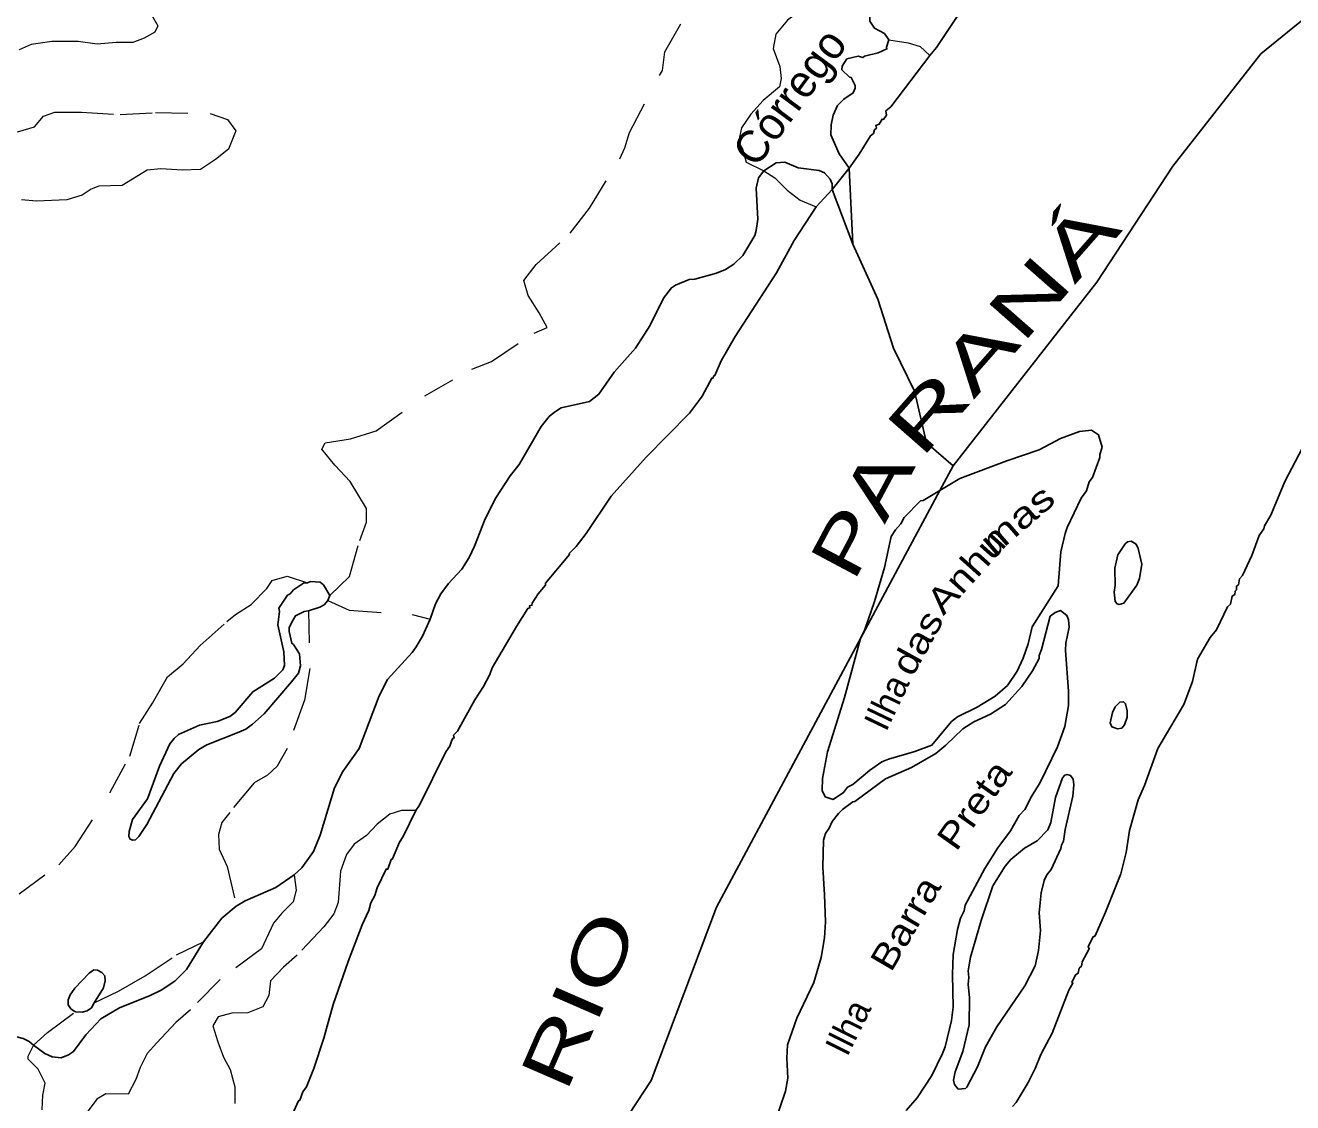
# Model space of a CAD drawing. Extents: x 344.9 to 371, y 7566.4 to 7594.3.
# Drawn here: x 362.817 to 366.76, y 7570.925 to 7574.277 of the extents above; entities that cross this region are included whole.
import ezdxf
from ezdxf.enums import TextEntityAlignment as Align

# ---------------------------------------------------------------- set-up
doc = ezdxf.new("R2010")
doc.units = 0
doc.header["$LTSCALE"] = 0.04
doc.linetypes.add('SHORT_DASHED', pattern=[2.7, 1.5, -1.2])
for name, color, linetype, lineweight in [('17', 7, 'SHORT_DASHED', 13), ('2', 7, 'Continuous', 25), ('21', 7, 'SHORT_DASHED', 13), ('55', 7, 'Continuous', 25), ('7', 7, 'Continuous', 25)]:
    doc.layers.add(name, color=color, linetype=linetype, lineweight=lineweight)
doc.layers.add('61', color=7, linetype='Continuous')

msp = doc.modelspace()

# ---------------------------------------------------------------- linework, layer by layer
at = {"layer": '17'}
for points in [[(365.3482, 7574.5062), (365.2817, 7574.4942), (365.2493, 7574.4831), (365.2438, 7574.4498), (365.2447, 7574.3657), (365.2401, 7574.3324), (365.1883, 7574.294), (365.1514, 7574.2497), (365.144, 7574.2053), (365.1643, 7574.1489), (365.168, 7574.112), (365.1634, 7574.0865), (365.1125, 7574.0431), (365.0737, 7574.0015), (365.0451, 7573.959), (365.0358, 7573.9146), (365.0478, 7573.893), (365.0599, 7573.8514), (365.1141, 7573.8251)], [(363.7646, 7572.5029), (363.8257, 7572.5619), (363.8573, 7572.6744), (363.8788, 7572.7313), (363.8788, 7572.7742), (363.827, 7572.8576), (363.7802, 7572.9082), (363.7398, 7572.9587), (363.7499, 7572.9783), (363.8283, 7572.991), (363.9079, 7573.015), (364.0595, 7573.1249), (364.2061, 7573.2077), (364.2667, 7573.2317), (364.3995, 7573.3195), (364.4399, 7573.3372), (364.4159, 7573.3827), (364.3818, 7573.4371), (364.3679, 7573.4838), (364.4058, 7573.5331), (364.5119, 7573.6304), (364.5726, 7573.7082), (364.6661, 7573.8623), (364.6825, 7573.8964), (364.6964, 7573.9444), (364.7988, 7574.1371), (364.8063, 7574.1953), (364.8961, 7574.3501)], [(365.5038, 7574.2325), (365.5635, 7574.2231), (365.6005, 7574.212), (365.6308, 7574.1841)], [(365.1141, 7573.8251), (365.1486, 7573.8024), (365.1874, 7573.7645), (365.2272, 7573.7331), (365.2774, 7573.7122)], [(362.7973, 7571.5743), (362.9208, 7571.6646), (362.9714, 7571.7215), (363.0813, 7571.8908), (363.142, 7572.0033), (363.1724, 7572.1045), (363.2128, 7572.1677), (363.2596, 7572.2498), (363.3076, 7572.2903), (363.3606, 7572.3471), (363.444, 7572.4217), (363.4706, 7572.4444), (363.5199, 7572.4747), (363.568, 7572.5253), (363.5844, 7572.5493), (363.6311, 7572.5632), (363.6948, 7572.5426)], [(363.7584, 7572.487), (363.8245, 7572.4571), (364.0203, 7572.4444), (364.076, 7572.4291)], [(363.6981, 7572.4554), (363.7018, 7572.2754), (363.6852, 7572.1776), (363.6317, 7572.0272), (363.6003, 7571.9719), (363.5708, 7571.9442), (363.5284, 7571.9202), (363.4527, 7571.828), (363.4287, 7571.7966), (363.4177, 7571.7597), (363.4195, 7571.7136), (363.4453, 7571.6601), (363.4733, 7571.5357)], [(364.0315, 7571.8336), (363.9873, 7571.8338), (363.9504, 7571.8228), (363.9117, 7571.7914), (363.8785, 7571.7563), (363.8397, 7571.7287), (363.8157, 7571.6973), (363.7973, 7571.6456), (363.7899, 7571.5479), (363.777, 7571.5128), (363.7456, 7571.4722), (363.6626, 7571.3837), (363.6202, 7571.3468), (363.5796, 7571.3043), (363.5741, 7571.2581), (363.5557, 7571.2231), (363.5095, 7571.2046), (363.4597, 7571.2028), (363.4173, 7571.1917), (363.4007, 7571.1641), (363.4154, 7571.1142), (363.4339, 7571.0663), (363.4542, 7571.0275), (363.4689, 7570.974), (363.4689, 7570.9224)], [(363.6536, 7571.6334), (363.6591, 7571.5864), (363.6499, 7571.5495), (363.6149, 7571.5144), (363.589, 7571.483), (363.5521, 7571.4037), (363.423, 7571.3078), (363.3307, 7571.2137), (363.2846, 7571.174), (363.2255, 7571.1113), (363.196, 7571.0781), (363.1739, 7571.0338), (363.161, 7570.9969), (363.137, 7570.9508), (363.0669, 7570.9526), (363.0392, 7570.936), (362.9875, 7570.8659)], [(363.031, 7571.2357), (363.1068, 7571.2719), (363.1898, 7571.3198), (363.2876, 7571.3844), (363.371, 7571.425)], [(362.8425, 7571.1035), (362.886, 7571.1435), (362.9726, 7571.2077)], [(362.8694, 7570.9019), (362.8713, 7570.948), (362.8787, 7570.9849), (362.8565, 7571.0292), (362.8252, 7571.0605), (362.8252, 7571.0697), (362.842, 7571.103), (362.8425, 7571.1035)]]:
    msp.add_lwpolyline(points, dxfattribs=at)
at = {"layer": '2'}
for points in [[(366.6473, 7575.1385), (366.451, 7574.9644), (366.3924, 7574.9074), (366.3011, 7574.8304), (366.2082, 7574.7756), (366.1264, 7574.7375), (366.0406, 7574.6851), (366.0231, 7574.6708), (365.9715, 7574.6184), (365.9199, 7574.5485), (365.8158, 7574.435), (365.7738, 7574.3842), (365.7349, 7574.3333), (365.6515, 7574.2087), (365.6308, 7574.1841)], [(365.6308, 7574.1841), (365.5093, 7574.0236), (365.4943, 7574.0109), (365.4958, 7573.9974), (365.4871, 7573.9847), (365.4823, 7573.9855), (365.4736, 7573.9704), (365.4625, 7573.9657), (365.4649, 7573.9577), (365.4585, 7573.9522), (365.4561, 7573.941), (365.4466, 7573.9339), (365.4107, 7573.8762), (365.3798, 7573.8333), (365.3272, 7573.7664), (365.2774, 7573.7122)], [(365.2774, 7573.7122), (365.2087, 7573.6074), (365.1544, 7573.5075), (365.025, 7573.309), (364.9821, 7573.2335), (364.9622, 7573.1875), (364.9582, 7573.1859), (364.9567, 7573.1795), (364.9523, 7573.1796), (364.9228, 7573.1235), (364.9108, 7573.1078)], [(364.9108, 7573.1078), (364.8831, 7573.0702), (364.7485, 7572.9338), (364.64, 7572.8117), (364.562, 7572.6959), (364.531, 7572.6554), (364.5088, 7572.634), (364.5096, 7572.6308), (364.4357, 7572.5411), (364.4349, 7572.5347), (364.4119, 7572.5085), (364.3937, 7572.4791), (364.3929, 7572.4727), (364.3857, 7572.4712), (364.3865, 7572.4648), (364.3802, 7572.4624), (364.3452, 7572.4069), (364.269, 7572.2782), (364.2618, 7572.2576), (364.242, 7572.2203), (364.215, 7572.1782), (364.161, 7572.0813), (364.1491, 7572.0686), (364.1515, 7572.0599), (364.1475, 7572.0591), (364.1435, 7572.0527), (364.1372, 7572.0337), (364.1252, 7572.0162), (364.0427, 7571.8502), (364.0315, 7571.8336)], [(366.835, 7573.0478), (366.7354, 7572.8579), (366.6917, 7572.7531), (366.6719, 7572.7197), (366.6703, 7572.7102), (366.656, 7572.6896), (366.633, 7572.6276)], [(365.8707, 7572.9222), (365.9707, 7572.9564), (366.0374, 7572.9921), (366.0962, 7573.0135), (366.1343, 7573.0175), (366.1557, 7573.0032), (366.1668, 7572.9643), (366.1597, 7572.9421), (366.1597, 7572.9325), (366.1375, 7572.8698), (366.1272, 7572.8571), (366.1184, 7572.8285), (366.1017, 7572.8055), (366.058, 7572.715), (366.0517, 7572.6959), (366.0382, 7572.6388), (366.0303, 7572.5331), (365.9493, 7572.4053), (365.9373, 7572.3529), (365.9215, 7572.3084), (365.9032, 7572.2671), (365.8722, 7572.2227), (365.8341, 7572.1893), (365.7786, 7572.1551), (365.7166, 7572.1257), (365.6984, 7572.1114), (365.6372, 7572.0376), (365.5848, 7572.0177), (365.5022, 7571.9939), (365.4816, 7571.9852), (365.4434, 7571.9582)], [(365.6623, 7572.8301), (365.7238, 7572.8674), (365.8707, 7572.9222)], [(365.4153, 7572.3691), (365.4291, 7572.3974), (365.4585, 7572.4839), (365.4903, 7572.5903), (365.511, 7572.6864), (365.5244, 7572.7078), (365.5411, 7572.7261), (365.5514, 7572.746), (365.6022, 7572.7976), (365.6102, 7572.7991), (365.6623, 7572.8301)], [(366.633, 7572.6276), (366.6036, 7572.5657), (366.5949, 7572.5545), (366.5917, 7572.5363), (366.5853, 7572.5316), (366.5853, 7572.5212), (366.5806, 7572.5164), (366.5798, 7572.5061), (366.5719, 7572.5014), (366.5663, 7572.4759), (366.5575, 7572.468), (366.5226, 7572.3958), (366.5035, 7572.3719), (366.4638, 7572.3052), (366.4479, 7572.2354), (366.4217, 7572.1639), (366.34, 7572.0273), (366.2987, 7571.9114), (366.2788, 7571.8669), (366.2518, 7571.7716), (366.2415, 7571.7033), (366.2256, 7571.6366), (366.178, 7571.5175), (366.1454, 7571.4436), (366.1391, 7571.4405), (366.124, 7571.4103), (366.1271, 7571.4039), (366.1049, 7571.3634), (366.1025, 7571.3492), (366.0954, 7571.3428), (366.0922, 7571.3277), (366.0843, 7571.3222), (366.0732, 7571.2991), (366.0763, 7571.2968), (366.0636, 7571.2745), (366.012, 7571.1411), (365.9763, 7571.0744), (365.9588, 7571.0315), (365.9365, 7570.9879), (365.8992, 7570.9251), (365.8881, 7570.9124)], [(363.6451, 7572.234), (363.5602, 7572.1347), (363.5237, 7572.1024), (363.5025, 7572.0874), (363.4808, 7572.0773), (363.3816, 7572.0382), (363.3562, 7572.0237), (363.3031, 7571.9787), (363.2786, 7571.9491), (363.1951, 7571.7902), (363.1697, 7571.7528), (363.1595, 7571.7431), (363.1517, 7571.7417), (363.1429, 7571.7445), (363.1392, 7571.7528), (363.1397, 7571.7687), (363.1498, 7571.8057), (363.1969, 7571.8698), (363.2343, 7571.9718), (363.2666, 7572.0415), (363.2795, 7572.0577), (363.2933, 7572.0706), (363.3584, 7572.0991), (363.4142, 7572.1113), (363.4534, 7572.1265), (363.4695, 7572.1394), (363.5249, 7572.2036), (363.5924, 7572.2457), (363.6178, 7572.2719), (363.6234, 7572.2853), (363.621, 7572.3275), (363.6027, 7572.4117), (363.6075, 7572.4537), (363.6059, 7572.464), (363.6329, 7572.5037), (363.6409, 7572.5085), (363.6512, 7572.5212), (363.6822, 7572.541), (363.6948, 7572.5426)], [(363.6948, 7572.5426), (363.7044, 7572.5466), (363.7338, 7572.5442), (363.7441, 7572.5363), (363.7646, 7572.5029), (363.7584, 7572.487)], [(363.7584, 7572.487), (363.7465, 7572.4743), (363.733, 7572.4664), (363.6981, 7572.4554)], [(363.6981, 7572.4554), (363.6845, 7572.4529), (363.6575, 7572.4402), (363.6504, 7572.4275)], [(365.3029, 7571.5715), (365.2981, 7571.6573), (365.3005, 7571.7414), (365.3068, 7571.7621), (365.318, 7571.7788), (365.3267, 7571.8002), (365.3466, 7571.8248), (365.3593, 7571.8375), (365.391, 7571.8605), (365.3974, 7571.8621), (365.4927, 7571.9328), (365.5737, 7571.9677), (365.6499, 7572.0114), (365.6809, 7572.0368), (365.7341, 7572.0884), (365.7682, 7572.1099), (365.8199, 7572.1337), (365.8659, 7572.1639), (365.9167, 7572.2203), (365.9501, 7572.2687), (365.9715, 7572.3068), (365.9707, 7572.3163), (365.9786, 7572.3354), (366.0049, 7572.4386), (366.0208, 7572.4497), (366.0374, 7572.4561), (366.0573, 7572.441), (366.0628, 7572.4275), (366.0642, 7572.4047)], [(363.6504, 7572.4275), (363.6377, 7572.4037), (363.6377, 7572.391), (363.6456, 7572.3544), (363.6512, 7572.3505), (363.6695, 7572.3219), (363.6726, 7572.2846), (363.6663, 7572.2615), (363.6451, 7572.234)], [(366.0642, 7572.4047), (366.0541, 7572.3545), (366.0533, 7572.3322), (366.0628, 7572.2052), (366.0628, 7572.1607), (366.0509, 7572.0956), (366.0279, 7572.0321), (365.9747, 7571.9209), (365.9469, 7571.878), (365.9263, 7571.8367), (365.9088, 7571.8184), (365.8818, 7571.7708), (365.8428, 7571.7176), (365.8024, 7571.6533), (365.7404, 7571.5389), (365.7373, 7571.5214), (365.7261, 7571.4984), (365.7174, 7571.4635), (365.7039, 7571.3857), (365.7015, 7571.3238), (365.7039, 7571.2221), (365.6983, 7571.1808), (365.6785, 7571.0982), (365.6705, 7571.0776), (365.6372, 7571.0093), (365.5911, 7570.9394), (365.557, 7570.9005)], [(365.4434, 7571.9582), (365.3918, 7571.9153), (365.3752, 7571.9066), (365.3624, 7571.8899), (365.3307, 7571.8685), (365.3052, 7571.8764), (365.2957, 7571.8963), (365.2973, 7571.9336), (365.3124, 7572.0162), (365.3656, 7572.1861), (365.4153, 7572.3691)], [(365.7904, 7571.4917), (365.827, 7571.5993), (365.8651, 7571.6604), (365.8826, 7571.6819), (365.9254, 7571.7168), (365.9644, 7571.7398), (365.9977, 7571.774), (366.0072, 7571.7962), (366.0223, 7571.8748), (366.044, 7571.9361), (366.0509, 7571.9435), (366.0587, 7571.9458), (366.0689, 7571.9431), (366.0767, 7571.9315), (366.079, 7571.9135), (366.0758, 7571.8785), (366.0517, 7571.7748), (366.0469, 7571.7383), (366.0406, 7571.7263), (366.039, 7571.7152), (366.008, 7571.6501), (365.9945, 7571.6334), (365.9866, 7571.616), (365.9771, 7571.5779), (365.9707, 7571.5159), (365.9755, 7571.4603), (365.9691, 7571.3984), (365.9588, 7571.3508), (365.927, 7571.288), (365.8397, 7571.1602), (365.8039, 7571.0982), (365.7793, 7571.0363), (365.746, 7570.9727), (365.742, 7570.9688), (365.719, 7570.9672)], [(364.0315, 7571.8336), (363.9926, 7571.7533), (363.9807, 7571.7351), (363.9593, 7571.6834), (363.9553, 7571.6819), (363.945, 7571.6517), (363.9394, 7571.6517), (363.9116, 7571.5937), (363.9045, 7571.5699), (363.8918, 7571.5461), (363.8854, 7571.5223), (363.8648, 7571.4778), (363.8211, 7571.3635)], [(365.339, 7570.7661), (365.3021, 7570.7472), (365.2433, 7570.6908), (365.2306, 7570.6726), (365.1846, 7570.6376), (365.1639, 7570.6416), (365.152, 7570.6535), (365.1353, 7570.7091), (365.129, 7570.7504), (365.1464, 7570.8568), (365.1814, 7570.9601), (365.1893, 7571.0014), (365.1861, 7571.0633), (365.1885, 7571.1046), (365.2171, 7571.1872), (365.2703, 7571.2983), (365.2933, 7571.3762), (365.3037, 7571.4381), (365.3061, 7571.4873), (365.3029, 7571.5715)], [(365.719, 7570.9672), (365.7079, 7570.9815), (365.7047, 7570.9942), (365.7102, 7571.0204), (365.7341, 7571.0839), (365.7531, 7571.1665), (365.7547, 7571.2507), (365.7499, 7571.2936), (365.7523, 7571.3142), (365.7499, 7571.3349), (365.7571, 7571.3778), (365.7904, 7571.4917)], [(363.8211, 7571.3635), (363.7743, 7571.2301), (363.7457, 7571.1252), (363.7147, 7571.0315), (363.6917, 7570.9743), (363.6806, 7570.9585), (363.671, 7570.9322), (363.6663, 7570.9299), (363.6472, 7570.887), (363.6377, 7570.8552), (363.6162, 7570.8028), (363.6004, 7570.7504), (363.5956, 7570.7155), (363.5884, 7570.698), (363.5614, 7570.5884), (363.5274, 7570.4931)], [(362.9687, 7571.2093), (362.9585, 7571.2168), (362.9504, 7571.2289), (362.9504, 7571.2444), (362.9562, 7571.2603), (362.9711, 7571.2814), (363.0152, 7571.3278), (363.0301, 7571.3377), (363.0419, 7571.3371), (363.0549, 7571.3296), (363.0642, 7571.319), (363.0649, 7571.3035), (363.0605, 7571.2824), (363.031, 7571.2357)], [(363.031, 7571.2357), (363.0232, 7571.2199), (363.0096, 7571.2106), (362.994, 7571.2068), (362.9726, 7571.2077), (362.9687, 7571.2093)]]:
    msp.add_lwpolyline(points, dxfattribs=at)
for points in [[(366.2391, 7572.6641), (366.2455, 7572.6697), (366.2574, 7572.6721), (366.2725, 7572.6633), (366.2796, 7572.6491), (366.2907, 7572.6006), (366.2836, 7572.5562), (366.2748, 7572.5355), (366.2344, 7572.4791), (366.2201, 7572.4751), (366.2137, 7572.4775), (366.2081, 7572.4847), (366.2042, 7572.5133), (366.2081, 7572.5339), (366.2065, 7572.5879), (366.2161, 7572.6292)], [(366.208, 7572.157), (366.1992, 7572.139), (366.1919, 7572.1067), (366.1969, 7572.0947), (366.2149, 7572.0882), (366.2283, 7572.09), (366.2366, 7572.1002), (366.2449, 7572.1249), (366.2449, 7572.1438), (366.2398, 7572.1664), (366.2338, 7572.1724), (366.2218, 7572.1706)]]:
    msp.add_lwpolyline(points, close=True, dxfattribs=at)
at = {"layer": '21'}
for points in [[(363.1939, 7574.3369), (363.2293, 7574.2756), (363.2199, 7574.2567), (363.1868, 7574.2379), (363.1515, 7574.2237), (363.0996, 7574.2237), (363.0406, 7574.219), (362.9816, 7574.2273), (362.8991, 7574.2273), (362.8354, 7574.2179), (362.7977, 7574.2014)], [(362.793, 7573.9456), (362.8449, 7573.9621), (362.8732, 7573.9951), (362.9086, 7574.0069), (362.9911, 7574.0069), (363.1114, 7573.9998), (363.2222, 7574.0057), (363.392, 7574.0034), (363.4463, 7573.9845), (363.4722, 7573.9492), (363.4486, 7573.8926), (363.4085, 7573.8595), (363.3614, 7573.8289), (363.3048, 7573.8265), (363.2387, 7573.8312), (363.1963, 7573.8265), (363.1185, 7573.7794), (363.0454, 7573.777), (363.0218, 7573.7676), (362.9935, 7573.7487), (362.9463, 7573.7346), (362.852, 7573.7299), (362.8048, 7573.7346)]]:
    msp.add_lwpolyline(points, dxfattribs=at)
at = {"layer": '55'}
for p in [(365.3798, 7573.8333), (365.3272, 7573.7664)]:
    msp.add_line(p, (365.3917, 7573.5968), dxfattribs=at)
for points in [[(367.4854, 7574.8196), (367.1023, 7574.5489), (366.6611, 7574.1888), (366.3867, 7573.8395), (366.1501, 7573.478), (365.7032, 7572.9063), (365.6623, 7572.8301), (365.4153, 7572.3691)], [(365.3917, 7573.5968), (365.4697, 7573.4257), (365.5175, 7573.2723), (365.5829, 7573.139), (365.6206, 7572.978), (365.7032, 7572.9063)], [(365.4153, 7572.3691), (364.9672, 7571.533), (364.7635, 7570.9941), (364.4224, 7570.4736), (364.2487, 7569.9432)]]:
    msp.add_lwpolyline(points, dxfattribs=at)
at = {"layer": '7'}
for points in [[(365.4628, 7574.3666), (365.4434, 7574.319), (365.4442, 7574.2905), (365.4585, 7574.269), (365.4895, 7574.2523), (365.5038, 7574.2325)], [(365.5038, 7574.2325), (365.4958, 7574.2095), (365.4974, 7574.2039), (365.4705, 7574.192), (365.4276, 7574.1816), (365.4228, 7574.1777), (365.4085, 7574.1816), (365.3728, 7574.1729), (365.3585, 7574.1507), (365.3577, 7574.1388), (365.3807, 7574.1165), (365.3863, 7574.115), (365.3982, 7574.0903), (365.3982, 7574.0816), (365.3926, 7574.0673), (365.3633, 7574.0474), (365.3442, 7574.0276), (365.3299, 7573.9982), (365.3243, 7573.9681), (365.3227, 7573.9363), (365.3489, 7573.8775), (365.3798, 7573.8333)], [(365.1141, 7573.8251), (365.0976, 7573.8027), (365.0911, 7573.7708), (365.0956, 7573.6742), (365.0909, 7573.6393), (365.0861, 7573.6234), (365.0496, 7573.5607), (365.021, 7573.5337), (364.9956, 7573.5178), (364.967, 7573.5067), (364.8995, 7573.4876), (364.882, 7573.4868), (364.8399, 7573.4693), (364.8272, 7573.4606), (364.8026, 7573.4281), (364.7597, 7573.3423), (364.7153, 7573.2732), (364.6493, 7573.1986), (364.6009, 7573.1295), (364.5716, 7573.1064), (364.4842, 7573.0866), (364.4628, 7573.0739), (364.4468, 7573.0596), (364.4222, 7573.0294)], [(365.3272, 7573.7664), (365.3268, 7573.7847), (365.3213, 7573.799), (365.3033, 7573.8188), (365.2862, 7573.8255), (365.2212, 7573.834), (365.1797, 7573.8516), (365.1525, 7573.8495), (365.1141, 7573.8251)], [(364.4222, 7573.0294), (364.3532, 7572.9103), (364.3253, 7572.8754), (364.2809, 7572.8071), (364.2475, 7572.742), (364.2142, 7572.6562), (364.1975, 7572.6213), (364.1745, 7572.5855), (364.1332, 7572.5403), (364.1094, 7572.5085), (364.0927, 7572.4768), (364.076, 7572.4291)], [(364.076, 7572.4291), (364.053, 7572.3767), (364.0331, 7572.3434), (364.0204, 7572.3259), (363.9434, 7572.2417), (363.918, 7572.1909), (363.8553, 7572.0273), (363.8044, 7571.9558), (363.779, 7571.905), (363.7338, 7571.7573), (363.7139, 7571.7065), (363.6774, 7571.6556), (363.6536, 7571.6334)], [(363.6536, 7571.6334), (363.5964, 7571.5945), (363.5011, 7571.5532), (363.4733, 7571.5357)], [(363.4733, 7571.5357), (363.428, 7571.4984), (363.371, 7571.425)], [(363.371, 7571.425), (363.3185, 7571.3396), (363.282, 7571.3031), (363.2391, 7571.2745), (363.2057, 7571.2578), (363.1096, 7571.2197), (363.0517, 7571.1855), (363.0048, 7571.1356), (362.9667, 7571.0839), (362.9508, 7571.0736), (362.9284, 7571.0644), (362.9008, 7571.0672), (362.8778, 7571.0775), (362.8425, 7571.1035)], [(362.8425, 7571.1035), (362.8293, 7571.1149), (362.8103, 7571.1245), (362.7821, 7571.1319), (362.7678, 7571.1301)]]:
    msp.add_lwpolyline(points, dxfattribs=at)

# ---------------------------------------------------------------- texts
at = {"layer": '61'}
for s, height, rotation, p in [('Córrego', 0.1, 53.52, (365.2348, 7574.0249)), ('Ilha', 0.08, 64.357, (365.5323, 7572.1538)), ('Ilha', 0.08, 63.455, (365.4122, 7571.1419))]:
    msp.add_text(s, height=height, rotation=rotation, dxfattribs=at).set_placement(p, align=Align.CENTER)
for s, height, rotation, width, p in [('RANÁ', 0.16, 48.665, 1.6, (365.9183, 7573.283)), ('PA', 0.16, 61.918, 1.45, (365.4905, 7572.7231)), ('mas', 0.08, 40.797, 1.3, (365.9286, 7572.7093)), ('Anhu', 0.08, 48.165, 1.2, (365.7734, 7572.5502)), ('das', 0.08, 60.945, 1.2, (365.6267, 7572.3371)), ('Preta', 0.08, 54.626, 1.2, (365.8017, 7571.8286)), ('Barra', 0.08, 59.621, 1.2, (365.5897, 7571.4629)), ('RIO', 0.16, 66.459, 1.5, (364.6132, 7571.214))]:
    msp.add_text(s, height=height, rotation=rotation, dxfattribs=dict(at, width=width)).set_placement(p, align=Align.CENTER)

doc.saveas('drawing.dxf')
